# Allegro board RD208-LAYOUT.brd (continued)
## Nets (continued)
GD_U3: Q7.4 R178.2 R216.1 R247.2
GD_U4: Q9.4 R179.2 R217.1 R249.2
GD_U5: Q11.4 R180.2 R218.1 R251.2
GD_U6: Q13.4 R181.2 R219.1 R253.2
GD_U7: Q15.4 R182.2 R220.1 R255.2
GD_U8: Q17.4 R183.2 R221.1 R257.2
GD_V1: Q19.4 R168.2 R222.1 R258.2
GD_V2: Q21.4 R169.2 R223.1 R260.2
GD_V3: Q23.4 R170.2 R224.1 R262.2
GD_V4: Q25.4 R171.2 R225.1 R266.2
GD_V5: Q27.4 R172.2 R226.1 R264.2
GD_V6: Q29.4 R173.2 R227.1 R268.2
GD_V7: Q31.4 R174.2 R228.1 R270.2
GD_V8: Q33.4 R175.2 R229.1 R272.2
GD_W1: Q35.4 R184.2 R230.1 R274.2
GD_W2: Q37.4 R185.2 R231.1 R276.2
GD_W3: Q39.4 R186.2 R232.1 R278.2
GD_W4: Q41.4 R187.2 R233.1 R280.2
GD_W5: Q43.4 R188.2 R234.1 R282.2
GD_W6: Q45.4 R189.2 R235.1 R284.2
GD_W7: Q47.4 R190.2 R236.1 R286.2
GD_W8: Q49.4 R191.2 R237.1 R288.2
HVU_1_4: C54.2 C56.1 D19.3 D19.4 D25.5 R195.2 R196.1
HVU_2_4: C49.2 C54.1 D17.3 D17.4 D23.5 R194.2 R195.1
HVU_3_4: C48.2 C49.1 D15.3 D15.4 D21.5 R193.2 R194.1
HVV_1_4: C69.2 C71.1 D31.3 D31.4 D37.5 R201.2 R202.1
HVV_2_4: C65.2 C69.1 D29.3 D29.4 D35.5 R200.2 R201.1
HVV_3_4: C63.2 C65.1 D27.3 D27.4 D33.5 R199.2 R200.1
HVW_1_4: C82.2 C84.1 D43.3 D43.4 D49.5 R205.2 R206.1
HVW_2_4: C80.2 C82.1 D41.3 D41.4 D47.5 R204.2 R205.1
HVW_3_4: C78.2 C80.1 D39.3 D39.4 D45.5 R203.2 R204.1
ILIM_H: IC13.3 IC15.3 IC18.3 R129.2 R131.1
ILIM_L: IC13.6 IC15.6 IC18.6 R132.2 R134.1
ISEN_U: IC10.7 IC19.1 R309.2
ISEN_U_FLT: C139.1 IC13.2 IC13.5 R309.1
ISEN_V: IC11.7 IC20.1 R310.2
ISEN_V_FLT: C140.1 IC15.2 IC15.5 R310.1
ISEN_W: IC12.7 IC21.1 R311.2
ISEN_W_FLT: C141.1 IC18.2 IC18.5 R311.1
L3803_FB: IC3.3 R29.2 R34.1
L3803_NGATE: IC3.6 R154.1
L3803_SENSE: C103.1 IC3.4 R30.1
L3803_VCC: C129.1 IC3.5 R155.2
LDO_15V_CDC: IC2.3 R296.1
LDO_15V_ILIM: IC2.2 R26.1
LDO_15V_SET: IC2.5 R27.2 R296.2
LDO_15V_STD_N: IC2.12 R22.2
LDO_15VOUT: C16.1 IC2.6 IC2.7 R21.1 R24.2 R25.1 R295.1 R297.2 TP4.1
LT8316_BIAS: C4.1 IC1.9 R2.1
LT8316_DCM: IC1.10 R4.2
LT8316_EN: C8.2 IC1.17 R7.2 R11.2 R312.2
LT8316_FB: IC1.12 R6.2 R12.1 R13.1
LT8316_FB_B: C5.1 D1.1 R6.1 T3.5
LT8316_GATE: IC1.19 R17.1
LT8316_GATE_B: Q1.1 R17.2 R207.1
LT8316_INTVCC: C14.1 IC1.8 R312.1
LT8316_IREG: IC1.14 R16.2
LT8316_SENSE: C13.1 IC1.18 R18.1
LT8316_SENSE_B: Q1.2 Q1.3 Q1.4 R18.2 R19.1
LT8316_TC: IC1.11 R12.2
LT8316_VC: C10.1 IC1.13 R14.1
MCU_EMG: CN3.25 IC16.7
MCU_IU: C134.1 CN3.36 R137.1
MCU_IV: C135.1 CN3.38 R140.1
MCU_IW: C136.1 CN3.40 R143.1
MCU_MODE: IC6.14 R44.2 R166.1
MCU_RESET: IC6.13 R45.2 R167.1
MCU_RSV1: IC6.12 R46.2 R198.2
MCU_RSV2: IC6.11 R47.2 R238.2
MCU_RSV3: IC8.12 R64.2 R239.2
MCU_RSV4: IC8.11 R65.2 R240.2
MCU_TCK: IC6.17 R41.2 R160.1
MCU_TDI: IC6.16 R42.2 R161.1
MCU_TDO: IC6.18 R40.2 R156.2
MCU_TMS: IC6.15 R43.2 R165.1
MCU_UH: IC8.18 R58.2 R162.1
MCU_UL: IC8.17 R59.2 R157.2
MCU_VDC: C133.1 CN3.26 R192.2
MCU_VH: IC8.16 R60.2 R163.1
MCU_VL: IC8.15 R61.2 R158.2
MCU_WH: IC8.14 R62.2 R164.1
MCU_WL: IC8.13 R63.2 R159.2
OC_U: IC14.7 IC17.1
OC_U_N: IC13.7 IC14.2
OC_U_P: IC13.1 IC14.1
OC_UV: IC16.1 IC17.7
OC_V: IC14.3 IC17.2
OC_V_N: IC14.6 IC15.7
OC_V_P: IC14.5 IC15.1
OC_W: IC16.2 IC17.3
OC_W_N: IC17.6 IC18.7
OC_W_P: IC17.5 IC18.1
OSC_ST_N: C46.1 IC22.1 IC22.4 R74.2
OUT_U: CN5.1 DR1.1
OUT_V: CN5.2 DR2.1
OUT_W: CN5.3 DR3.1
PC_ANODE_U1: C142.1 PC1.1 R81.2 R337.1
PC_ANODE_U2: C143.1 PC2.1 R83.2 R338.1
PC_ANODE_U3: C144.1 PC3.1 R85.2 R339.1
PC_ANODE_U4: C145.1 PC4.1 R87.2 R340.1
PC_ANODE_U5: C146.1 PC5.1 R89.2 R341.1
PC_ANODE_U6: C147.1 PC6.1 R91.2 R342.1
PC_ANODE_U7: C148.1 PC7.1 R93.2 R343.1
PC_ANODE_U8: C149.1 PC8.1 R95.2 R344.1
PC_ANODE_V1: C150.1 PC9.1 R97.2 R345.1
PC_ANODE_V2: C151.1 PC10.1 R99.2 R346.1
PC_ANODE_V3: C152.1 PC11.1 R100.2 R347.1
PC_ANODE_V4: C153.1 PC12.1 R102.2 R348.1
PC_ANODE_V5: C154.1 PC13.1 R105.2 R349.1
PC_ANODE_V6: C155.1 PC14.1 R107.2 R350.1
PC_ANODE_V7: C156.1 PC15.1 R109.2 R351.1
PC_ANODE_V8: C157.1 PC16.1 R111.2 R352.1
PC_ANODE_W1: C158.1 PC17.1 R113.2 R353.1
PC_ANODE_W2: C159.1 PC18.1 R115.2 R354.1
PC_ANODE_W3: C160.1 PC19.1 R117.2 R355.1
PC_ANODE_W4: C161.1 PC20.1 R119.2 R356.1
PC_ANODE_W5: C162.1 PC21.1 R121.2 R357.1
PC_ANODE_W6: C163.1 PC22.1 R123.2 R358.1
PC_ANODE_W7: C164.1 PC23.1 R125.2 R359.1
PC_ANODE_W8: C165.1 PC24.1 R127.2 R360.1
PC_G_U1: C47.2 C112.2 D15.5 PC1.4 Q3.1 Q3.2 Q3.3 Q5.5 Q5.6 Q5.7 Q5.8 R214.2 TP65.1
PC_G_U2: C50.2 C113.2 D17.5 PC2.4 Q5.1 Q5.2 Q5.3 Q7.5 Q7.6 Q7.7 Q7.8 R215.2 TP66.1
PC_G_U3: C53.2 C114.2 D19.5 PC3.4 Q7.1 Q7.2 Q7.3 Q9.5 Q9.6 Q9.7 Q9.8 R216.2 TP67.1
PC_G_U5: C57.2 C116.2 D21.3 D21.4 PC5.4 Q11.1 Q11.2 Q11.3 Q13.5 Q13.6 Q13.7 Q13.8 R218.2 TP69.1
PC_G_U6: C58.2 C117.2 D23.3 D23.4 PC6.4 Q13.1 Q13.2 Q13.3 Q15.5 Q15.6 Q15.7 Q15.8 R219.2 TP70.1
PC_G_U7: C59.2 C118.2 D25.3 D25.4 PC7.4 Q15.1 Q15.2 Q15.3 Q17.5 Q17.6 Q17.7 Q17.8 R220.2 TP71.1
PC_G_U8: C60.2 C119.2 IC10.1 IC10.2 PC8.4 Q17.1 Q17.2 Q17.3 R221.2 TP72.1
PC_G_V1: C62.2 C104.2 D27.5 PC9.4 Q19.1 Q19.2 Q19.3 Q21.5 Q21.6 Q21.7 Q21.8 R222.2 TP73.1
PC_G_V2: C64.2 C105.2 D29.5 PC10.4 Q21.1 Q21.2 Q21.3 Q23.5 Q23.6 Q23.7 Q23.8 R223.2 TP74.1
PC_G_V3: C68.2 C106.2 D31.5 PC11.4 Q23.1 Q23.2 Q23.3 Q25.5 Q25.6 Q25.7 Q25.8 R224.2 TP75.1
PC_G_V5: C72.2 C108.2 D33.3 D33.4 PC13.4 Q27.1 Q27.2 Q27.3 Q29.5 Q29.6 Q29.7 Q29.8 R226.2 TP77.1
PC_G_V6: C73.2 C109.2 D35.3 D35.4 PC14.4 Q29.1 Q29.2 Q29.3 Q31.5 Q31.6 Q31.7 Q31.8 R227.2 TP78.1
PC_G_V7: C74.2 C110.2 D37.3 D37.4 PC15.4 Q31.1 Q31.2 Q31.3 Q33.5 Q33.6 Q33.7 Q33.8 R228.2 TP79.1
PC_G_V8: C76.2 C111.2 IC11.1 IC11.2 PC16.4 Q33.1 Q33.2 Q33.3 R229.2 TP80.1
PC_G_W1: C77.2 C120.2 D39.5 PC17.4 Q35.1 Q35.2 Q35.3 Q37.5 Q37.6 Q37.7 Q37.8 R230.2 TP81.1
PC_G_W2: C79.2 C121.2 D41.5 PC18.4 Q37.1 Q37.2 Q37.3 Q39.5 Q39.6 Q39.7 Q39.8 R231.2 TP82.1
PC_G_W3: C81.2 C122.2 D43.5 PC19.4 Q39.1 Q39.2 Q39.3 Q41.5 Q41.6 Q41.7 Q41.8 R232.2 TP83.1
PC_G_W5: C85.2 C124.2 D45.3 D45.4 PC21.4 Q43.1 Q43.2 Q43.3 Q45.5 Q45.6 Q45.7 Q45.8 R234.2 TP85.1
PC_G_W6: C86.2 C125.2 D47.3 D47.4 PC22.4 Q45.1 Q45.2 Q45.3 Q47.5 Q47.6 Q47.7 Q47.8 R235.2 TP86.1
PC_G_W7: C87.2 C126.2 D49.3 D49.4 PC23.4 Q47.1 Q47.2 Q47.3 Q49.5 Q49.6 Q49.7 Q49.8 R236.2 TP87.1
PC_G_W8: C88.2 C127.2 IC12.1 IC12.2 PC24.4 Q49.1 Q49.2 Q49.3 R237.2 TP88.1
PC_GD_U1: D50.K PC1.5 R176.1
PC_GD_U2: D51.K PC2.5 R177.1
PC_GD_U3: D52.K PC3.5 R178.1
PC_GD_U4: D53.K PC4.5 R179.1
PC_GD_U5: D54.K PC5.5 R180.1
PC_GD_U6: D55.K PC6.5 R181.1
PC_GD_U7: D56.K PC7.5 R182.1
PC_GD_U8: D57.K PC8.5 R183.1
PC_GD_V1: D58.K PC9.5 R168.1
PC_GD_V2: D59.K PC10.5 R169.1
PC_GD_V3: D60.K PC11.5 R170.1
PC_GD_V4: D62.K PC12.5 R171.1
PC_GD_V5: D61.K PC13.5 R172.1
PC_GD_V6: D63.K PC14.5 R173.1
PC_GD_V7: D64.K PC15.5 R174.1
PC_GD_V8: D65.K PC16.5 R175.1
PC_GD_W1: D66.K PC17.5 R184.1
PC_GD_W2: D67.K PC18.5 R185.1
PC_GD_W3: D68.K PC19.5 R186.1
PC_GD_W4: D69.K PC20.5 R187.1
PC_GD_W5: D70.K PC21.5 R188.1
PC_GD_W6: D71.K PC22.5 R189.1
PC_GD_W7: D72.K PC23.5 R190.1
PC_GD_W8: D73.K PC24.5 R191.1
PC_V_U1: C47.1 C112.1 PC1.6 R80.1 TP25.1
PC_V_U2: C50.1 C113.1 PC2.6 R82.1 TP26.1
PC_V_U3: C53.1 C114.1 PC3.6 R84.1 TP27.1
PC_V_U4: C55.1 C115.1 PC4.6 R86.1 TP28.1
PC_V_U5: C57.1 C116.1 PC5.6 R88.1 TP29.1
PC_V_U6: C58.1 C117.1 PC6.6 R90.1 TP30.1
PC_V_U7: C59.1 C118.1 PC7.6 R92.1 TP31.1
PC_V_U8: C60.1 C119.1 PC8.6 R94.1 TP32.1
PC_V_V1: C62.1 C104.1 PC9.6 R96.1 TP41.1
PC_V_V2: C64.1 C105.1 PC10.6 R98.1 TP42.1
PC_V_V3: C68.1 C106.1 PC11.6 R101.1 TP43.1
PC_V_V4: C70.1 C107.1 PC12.6 R103.1 TP44.1
PC_V_V5: C72.1 C108.1 PC13.6 R104.1 TP45.1
PC_V_V6: C73.1 C109.1 PC14.6 R106.1 TP46.1
PC_V_V7: C74.1 C110.1 PC15.6 R108.1 TP47.1
PC_V_V8: C76.1 C111.1 PC16.6 R110.1 TP48.1
PC_V_W1: C77.1 C120.1 PC17.6 R112.1 TP57.1
PC_V_W2: C79.1 C121.1 PC18.6 R114.1 TP58.1
PC_V_W3: C81.1 C122.1 PC19.6 R116.1 TP59.1
PC_V_W4: C83.1 C123.1 PC20.6 R118.1 TP60.1
PC_V_W5: C85.1 C124.1 PC21.6 R120.1 TP61.1
PC_V_W6: C86.1 C125.1 PC22.6 R122.1 TP62.1
PC_V_W7: C87.1 C126.1 PC23.6 R124.1 TP63.1
PC_V_W8: C88.1 C127.1 PC24.6 R126.1 TP64.1
PC_VGS_U1: C142.2 PC1.3 Q4.3 R337.2
PC_VGS_U2: C143.2 PC2.3 Q6.3 R338.2
PC_VGS_U3: C144.2 PC3.3 Q8.3 R339.2
PC_VGS_U4: C145.2 PC4.3 Q10.3 R340.2
PC_VGS_U5: C146.2 PC5.3 Q12.3 R341.2
PC_VGS_U6: C147.2 PC6.3 Q14.3 R342.2
PC_VGS_U7: C148.2 PC7.3 Q16.3 R343.2
PC_VGS_U8: C149.2 PC8.3 Q18.3 R344.2
PC_VGS_V1: C150.2 PC9.3 Q20.3 R345.2
PC_VGS_V2: C151.2 PC10.3 Q22.3 R346.2
PC_VGS_V3: C152.2 PC11.3 Q24.3 R347.2
PC_VGS_V4: C153.2 PC12.3 Q26.3 R348.2
PC_VGS_V5: C154.2 PC13.3 Q28.3 R349.2
PC_VGS_V6: C155.2 PC14.3 Q30.3 R350.2
PC_VGS_V7: C156.2 PC15.3 Q32.3 R351.2
PC_VGS_V8: C157.2 PC16.3 Q34.3 R352.2
PC_VGS_W1: C158.2 PC17.3 Q36.3 R353.2
PC_VGS_W2: C159.2 PC18.3 Q38.3 R354.2
PC_VGS_W3: C160.2 PC19.3 Q40.3 R355.2
PC_VGS_W4: C161.2 PC20.3 Q42.3 R356.2
PC_VGS_W5: C162.2 PC21.3 Q44.3 R357.2
PC_VGS_W6: C163.2 PC22.3 Q46.3 R358.2
PC_VGS_W7: C164.2 PC23.3 Q48.3 R359.2
PC_VGS_W8: C165.2 PC24.3 Q50.3 R360.2
TRANS2_AUX: D10.A T2.3
TRANS2_AUX_B: C21.1 D10.K R28.1 R31.1 R300.1
TRANS2_PRI: C128.1 Q2.5 Q2.6 Q2.7 Q2.8 T2.1
TRANS2_SEC1: D7.A T2.16
TRANS2_SEC2: D8.A T2.13
TRANS2_SEC3: D9.A T2.10
TRANS2_SEC4: D11.A T2.7
V_LH: C20.1 D11.K D20.A D22.A D24.A D32.A D34.A D36.A D44.A D46.A D48.A R94.2 R110.2 R126.2 R307.1 R308.1
V_UH: C17.1 D7.K D14.A D16.A D18.A R86.2 R301.1 R302.1
V_UL: C17.2 C55.2 C115.2 DR1.2 PC4.4 Q9.1 Q9.2 Q9.3 Q11.5 Q11.6 Q11.7 Q11.8 R217.2 R301.2 R302.2 T2.15 TP68.1
V_VH: C18.1 D8.K D26.A D28.A D30.A R103.2 R303.1 R304.1
V_VL: C18.2 C70.2 C107.2 DR2.2 PC12.4 Q25.1 Q25.2 Q25.3 Q27.5 Q27.6 Q27.7 Q27.8 R225.2 R303.2 R304.2 T2.12 TP76.1
V_WH: C19.1 D9.K D38.A D40.A D42.A R118.2 R305.1 R306.1
V_WL: C19.2 C83.2 C123.2 DR3.2 PC20.4 Q41.1 Q41.2 Q41.3 Q43.5 Q43.6 Q43.7 Q43.8 R233.2 R305.2 R306.2 T2.9 TP84.1
VDC: C11.1 C130.1 IC9.1 R10.2 R15.1
VDC_VF_OUT: IC9.3 IC9.4 R192.1
VP_1R8_CPLD_D: C30.1 C40.1 C41.1 C42.1 IC5.5 IC7.26 IC7.57 TP8.1
VP_3R3_PRH_D: C25.1 C31.1 C32.1 C33.1 C34.1 C35.1 C36.1 C37.1 C39.1 C44.1 C61.1 C75.1 C89.1 CN4.2 IC4.5 IC6.1 IC7.5 IC7.20 IC7.38 IC7.51 IC7.88 IC7.98 IC8.1 IC10.8 IC11.8 IC12.8 R48.1 R49.1 R50.1 R51.1 R52.1 R53.1 R54.1 R55.1 R66.1 R67.1 R68.1 R69.1 R70.1 R71.1 R72.1 R73.1 R74.1 R128.1 R129.1 R145.1 R146.1 R147.1 R148.1 R149.1 R150.1 R151.1 R152.1 R153.1 R241.1 R243.1 R289.2 R291.2 R293.2 TP7.1
VP_5R0_PRH_D: C27.1 C28.1 C29.1 C38.1 C43.1 C45.1 C90.1 C91.1 C92.1 C93.1 C94.1 C95.1 C97.1 C99.1 C101.1 FL1.3 IC4.1 IC5.1 IC6.20 IC8.20 IC9.5 IC13.8 IC14.8 IC15.8 IC16.8 IC17.8 IC18.8 IC19.5 IC20.5 IC21.5 R36.1 R39.1 R40.1 R41.1 R42.1 R43.1 R44.1 R45.1 R46.1 R47.1 R56.2 R57.2 R58.1 R59.1 R60.1 R61.1 R62.1 R63.1 R64.1 R65.1 R81.1 R83.1 R85.1 R87.1 R89.1 R91.1 R93.1 R95.1 R97.1 R99.1 R100.1 R102.1 R105.1 R107.1 R109.1 R111.1 R113.1 R115.1 R117.1 R119.1 R121.1 R123.1 R125.1 R127.1 TP6.1
VP_15R0_INV_ISO: C137.1 C138.1 R20.2 R21.2 R23.2 R25.2 R155.1 T2.2 TP5.1
VP_15R0_INV_LDO: C6.1 C7.1 C9.1 C15.1 C131.1 C132.1 D2.3 D3.K IC2.10 IC2.11 R8.2 R20.1 R22.1 R23.1 TP3.1
VP_400R0_INV: C1.1 C2.1 C3.1 C48.1 C63.1 C66.1 C67.1 C78.1 CN1.1 D4.A IC1.1 IC1.2 IC1.3 Q3.5 Q3.6 Q3.7 Q3.8 Q19.5 Q19.6 Q19.7 Q19.8 Q35.5 Q35.6 Q35.7 Q35.8 R1.1 R5.1 R193.1 R199.1 R203.1 T3.3 TP1.1
N757857: D6.A Q1.5 T3.1
N3161846: Q2.1 Q2.2 Q2.3 R30.2 R33.1
N3164696: C22.1 IC3.1
N3166714: C22.2 R32.1
N7602621: D1.2 R2.2
N15775681: R131.2 R133.1
N15775685: R133.2 R135.1
N15775892: R130.2 R132.1
N15776035: R128.2 R130.1
N15787951: IC6.19 R241.2 R242.2
N15791319: IC8.19 R243.2 R244.2
N15816177: CN3.20 R56.1
N15836565: CN3.28 R57.1
N15837078: CN3.10 R157.1
N15837084: CN3.12 R158.1
N15837090: CN3.14 R159.1
N15837096: CN3.4 R156.1
N15859536: IC10.6 R289.1 R290.1
N15862955: IC12.6 R293.1 R294.2
N15947158: R9.2 R10.1
N15947162: R5.2 R9.1
N15947280: R1.2 R3.1
N15947304: R3.2 R7.1
N15966322: IC22.3 R79.1
N15969728: DS1.A R145.2
N15969732: DS2.A R146.2
N15969736: DS3.A R147.2
N15969740: DS4.A R148.2
N15970009: R149.2 R210.1 S1.1
N15970013: R150.2 R211.1 S1.2
N15970017: R151.2 R212.1 S1.3
N15970021: R152.2 R213.1 S1.4
N15981855: C102.1 R153.2 R209.1 S2.1 S2.2
N16080427: Q2.4 R154.2 R208.1
N16084254: CN3.3 R160.2
N16084299: CN3.5 R161.2
N16084344: CN3.9 R162.2
N16084389: CN3.11 R163.2
N16084434: CN3.13 R164.2
N16084479: CN3.19 R165.2
N16084524: CN3.21 R166.2
N16084569: CN3.23 R167.2
N16128748: D2.1 D2.2 T3.8 T3.9
N16129695: D4.K D6.K
N16132048: CN3.6 R198.1
N16289804: C128.2 R197.1
N16355511: C5.2 R4.1
N16465335: IC4.3 R36.2
N16465385: IC5.3 R39.2
N16663040: CN3.8 R238.1
N16663424: CN3.22 R239.1
N16663428: CN3.24 R240.1
N16677268: D50.A R245.1
N16677456: D51.A R246.1
N16677751: D52.A R247.1
N16678100: D53.A R249.1
N16678365: D54.A R251.1
N16678572: D55.A R253.1
N16678779: D56.A R255.1
N16678984: D57.A R257.1
N16682431: D58.A R258.1
N16682896: D59.A R260.1
N16683103: D60.A R262.1
N16683312: D61.A R264.1
N16683534: D62.A R266.1
N16683743: D63.A R268.1
N16683946: D64.A R270.1
N16684168: D65.A R272.1
N16689205: D66.A R274.1
N16689414: D67.A R276.1
N16689619: D68.A R278.1
N16689826: D69.A R280.1
N16690061: D70.A R282.1
N16690281: D71.A R284.1
N16690501: D72.A R286.1
N16690719: D73.A R288.1
N16776249: IC11.6 R291.1 R292.2
N16781117: IC2.15 R295.2
N16783087: R24.1 R27.1
N16783507: IC2.4 R297.1
N159286810: C12.1 R14.2
N159479370: R28.2 R29.1

Pads without a net: CN3 7 17 18 27 30 32 34; CN4 12 14; D15 1 2; D17 1 2; D19 1 2; D21 1 2; D23 1 2; D25 1 2; D27 1 2; D29 1 2; D31 1 2; D33 1 2; D35 1 2; D37 1 2; D39 1 2; D41 1 2; D43 1 2; D45 1 2; D47 1 2; D49 1 2; IC2 13 14; IC4 4; IC5 4; IC7 1 2 3 4 6 15 16 17 18 19 29 37 39 40 41 42 43 44 46 59 63 64 74 86 87 97; IC16 3; T3 2 4 7 12

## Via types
v1: diameter 0.6, hole 0.3, TOP to BOTTOM, 502 vias
v2: diameter 0.8, hole 0.5, TOP to BOTTOM, 1431 vias
v3: diameter 1.6, hole 1, TOP to BOTTOM, 1 via

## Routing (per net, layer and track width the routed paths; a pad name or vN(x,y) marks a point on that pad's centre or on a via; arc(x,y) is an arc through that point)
GND: length 239.3
  TOP w0.35: IC1.21 48.8,18.98 52.1,18.98 v2(52.75,18.32) IC1.15 48.8,18.32 IC1.21 ; IC1.21 48.47,21.57 IC1.20 52.1,21.57 52.33,21.8 C13.2 ; IC2.1 IC2.16 ; IC2.9 IC2.8
  TOP w0.5: R26.2 162.85,30.95 ; C12.2 58.25,14.75
  TOP w0.6: v1(196.35,3.75) v1(197.35,3.75) ; 186,144.2 185.71,143.91 IC12.4 ; IC11.3 163.49,97.2 ; IC12.3 185.63,142.63 186,143 ; 164.85,97.25 164.75,97.34 IC11.4 ; IC10.4 58.25,59.24 ; IC10.3 58.25,60.52 ; v1(196.35,5.5) v1(197.35,5.5)
  TOP w0.8: R298.2 61.4,148.15 ; R298.2 R299.2 ; R298.2 60.25,147 ; R299.2 60.25,144.5 ; R299.2 61.4,143.5 ; C10.2 56.7,13.25 ; R207.2 v1(50.5,23.1) ; R16.1 56.7,16.25 ; R13.2 56.7,11.75
  TOP w1: C4.2 45.12,8.2 ; IC2.17 v2(157.5,37.5) ; v2(48.45,22.2) 48.45,19.85 ; 56.7,16.25 R19.2 ; R19.2 58.05,18.7 ; R19.2 v2(55.1,18.7) ; C15.2 154.4,38.85 ; C14.2 38.5,13.1 ; C16.2 161.1,38.95
  CONDUCTIVE4 w3: 54.1,138.85 54.1,134.85 46.65,127.4 46.65,63.65 34.75,51.75 C66.2
  BOTTOM w0.6: C138.2 v1(196.35,5.5) v1(197.35,5.5) ; v1(197.35,3.75) v1(196.35,3.75) C137.2 ; v1(189.5,25) IC3.2 191.9,25 v1(192.15,25.25) ; R31.2 v1(200.15,20.25) 200.6,19.8 C21.2 v1(201.8,18.25)
  BOTTOM w0.8: R32.2 v1(195.6,26.2) ; R197.2 v1(193.1,13.05) ; C20.2 224,13.9 R307.2 R308.2 ; R34.2 v1(195.25,24.05) ; R208.2 v1(191.3,16.9) ; R33.2 189.76,21.01 v1(189.95,21.2) C103.2 189.95,23.1 189.5,23.55 v1(189.5,25) 189.5,27.5 188.8,28.2 v1(187.7,28.2) C129.2 ; R11.1 49.5,15.7 ; C8.1 51,16 ; R300.2 R31.2
  BOTTOM w1: C20.2 T2.8
  BOTTOM w1.2: C56.2 11.85,87.4 R196.2
  BOTTOM w1.3: R206.2 227.35,128.6 C84.2 ; R202.2 156.1,56.35 C71.2
  vias: v2(10.7,11.5) v2(10.7,10.3) v2(10.7,9.1) v2(10.7,7.9) v2(10.7,6.7) v2(10.7,5.5) v2(11.9,11.5) v2(11.9,10.3) v2(11.9,9.1) v2(11.9,7.9) v2(11.9,6.7) v2(11.9,5.5) v2(13.1,11.5) v2(13.1,10.3) v2(13.1,9.1) v2(13.1,7.9) v2(13.1,6.7) v2(13.1,5.5) v2(14.3,11.5) v2(14.3,10.3) v2(14.3,9.1) v2(14.3,7.9) v2(14.3,6.7) v2(14.3,5.5) v2(15.5,11.5) v2(15.5,10.3) v2(15.5,9.1) v2(15.5,7.9) v2(15.5,6.7) v2(15.5,5.5) v2(16.7,11.5) v2(16.7,10.3) v2(16.7,9.1) v2(16.7,7.9) v2(16.7,6.7) v2(16.7,5.5) v2(17.9,11.5) v2(17.9,10.3) v2(17.9,9.1) v2(17.9,7.9) v2(17.9,6.7) v2(17.9,5.5) v2(19.1,11.5) v2(19.1,10.3) v2(19.1,9.1) v2(19.1,7.9) v2(19.1,6.7) v2(19.1,5.5) v2(27.6,7.6) v2(27.6,6.4) v2(27.6,5.2) v2(27.6,4) v2(27.6,2.8) v2(28.7,61.85) v2(28.7,60.65) v2(28.7,59.45) v2(28.7,58.25) v2(28.7,57.05) v2(28.7,55.85) v2(28.8,7.6) v2(28.8,6.4) v2(28.8,5.2) v2(28.8,4) v2(28.8,2.8) v2(29.9,61.85) v2(29.9,60.65) v2(29.9,59.45) v2(29.9,58.25) v2(29.9,57.05) v2(29.9,55.85) v2(30,7.6) v2(30,6.4) v2(30,5.2) v2(30,4) v2(30,2.8) v2(31.1,61.85) v2(31.1,60.65) v2(31.1,59.45) v2(31.1,58.25) v2(31.1,57.05) v2(31.1,55.85) v2(31.2,7.6) v2(31.2,6.4) v2(31.2,5.2) v2(31.2,4) v2(31.2,2.8) v2(32.3,61.85) v2(32.3,60.65) v2(32.3,59.45) v2(32.3,58.25) v2(32.3,57.05) v2(32.3,55.85) v2(32.4,8.8) v2(32.4,7.6) v2(32.4,6.4) v2(32.4,5.2) v2(32.4,4) v2(32.4,2.8) v2(33.5,61.85) v2(33.5,60.65) v2(33.5,59.45) v2(33.5,58.25) v2(33.5,57.05) v2(33.5,55.85) v2(33.6,8.8) v2(33.6,7.6) v2(33.6,6.4) v2(33.6,5.2) v2(33.6,4) v2(33.6,2.8) v2(34.7,61.85) v2(34.7,60.65) v2(34.7,59.45) v2(34.7,58.25) v2(34.7,57.05) v2(34.7,55.85) v2(34.8,8.8) v2(34.8,7.6) v2(34.8,6.4) v2(34.8,5.2) v2(34.8,4) v2(34.8,2.8) v2(35.9,61.85) v2(35.9,60.65) v2(35.9,59.45) v2(35.9,58.25) v2(35.9,57.05) v2(36,12.4) v2(36,11.2) v2(36,10) v2(36,8.8) v2(36,7.6) v2(36,6.4) v2(36,5.2) v2(36,4) v2(36,2.8) v2(37.2,12.4) v2(37.2,11.2) v2(37.2,10) v2(37.2,8.8) v2(37.2,7.6) v2(37.2,4) v2(37.2,2.8) v2(38.4,12.4) v2(38.4,11.2) v2(38.4,10) v2(38.4,8.8) v2(38.4,7.6) v2(38.4,4) v2(38.4,2.8) v2(39.6,8.8) v2(39.6,7.6) v2(39.6,6.4) v2(39.6,5.2) v2(39.6,4) v2(39.6,2.8) v2(40.8,8.8) v2(40.8,7.6) v2(40.8,6.4) v2(40.8,5.2) v2(40.8,4) v2(40.8,2.8) v2(42,8.8) v2(42,7.6) v2(42,6.4) v2(42,5.2) v2(42,4) v2(42,2.8) v2(46.15,14.75) v2(47.35,14.75) v2(48.55,14.75) v2(49.75,14.75) v2(53.9,18.7) v2(53.9,17.5) v2(55.1,17.5) v2(57.85,148.1) v2(57.85,146.9) v2(59.05,148.1) v2(59.05,146.9) v2(60.25,148.1) v2(60.25,146.9) v2(61.7,7.5) v2(61.7,6.3) v2(61.7,5.1) v2(61.7,3.9) v2(61.7,2.7) v2(62.9,7.5) v2(62.9,6.3) v2(62.9,5.1) v2(62.9,3.9) v2(62.9,2.7) v2(64.1,7.5) v2(64.1,6.3) v2(64.1,5.1) v2(64.1,3.9) v2(64.1,2.7) v2(65.3,7.5) v2(65.3,6.3) v2(65.3,5.1) v2(65.3,3.9) v2(65.3,2.7) v2(66.5,7.5) v2(66.5,6.3) v2(66.5,5.1) v2(66.5,3.9) v2(66.5,2.7) v2(99.1,25.45) v2(99.1,24.25) v2(99.1,23.05) v2(99.1,21.85) v2(99.1,20.65) v2(100.3,25.45) v2(100.3,24.25) v2(100.3,23.05) v2(100.3,21.85) v2(100.3,20.65) v2(155.1,37.5) v2(155.1,31) v2(156.3,37.5) v2(156.3,31) v2(157.5,31) v2(158.7,37.5) v2(158.7,31) v2(159.9,37.5) v2(159.9,31) v2(164.75,97.25) v2(164.75,96.05) v2(164.75,94.85) v2(164.75,93.65) v2(165.95,97.25) v2(165.95,96.05) v2(165.95,94.85) v2(165.95,93.65) v2(165.95,92.45) v2(167.15,98.45) v2(167.15,97.25) v2(167.15,96.05) v2(167.15,94.85) v2(167.15,93.65) v2(167.15,92.45) v2(167.15,91.25) v2(168.35,98.45) v2(168.35,97.25) v2(168.35,96.05) v2(168.35,94.85) v2(168.35,93.65) v2(168.35,92.45) v2(168.35,91.25) v2(168.35,90.05) v2(169.55,98.45) v2(169.55,97.25) v2(169.55,96.05) v2(169.55,94.85) v2(169.55,93.65) v2(169.55,92.45) v2(169.55,91.25) v2(169.55,90.05) v2(169.55,88.85) v2(170.75,97.25) v2(170.75,96.05) v2(170.75,94.85) v2(170.75,93.65) v2(170.75,92.45) v2(170.75,91.25) v2(170.75,90.05) v2(170.75,88.85) v2(186,147.9) v2(186,146.7) v2(186,145.5) v2(186,144.3) v2(186,143.1) v2(187.2,147.9) v2(187.2,146.7) v2(187.2,145.5) v2(187.2,144.3) v2(187.2,143.1) v2(188.4,147.9) v2(188.4,146.7) v2(188.4,145.5) v2(188.4,144.3) v2(188.4,143.1) v2(189.6,147.9) v2(189.6,146.7) v2(189.6,145.5) v2(189.6,144.3) v2(189.6,143.1) v2(190.8,147.9) v2(190.8,146.7) v2(190.8,145.5) v2(190.8,144.3) v2(190.8,143.1) v2(192,147.9) v2(192,146.7) v2(192,145.5) v2(192,144.3) v2(192,143.1) v2(193.2,147.9) v2(193.2,146.7) v2(193.2,145.5) v2(193.2,144.3) v2(193.2,143.1) v2(194.4,147.9) v2(194.4,146.7) v2(194.4,145.5) v2(194.4,144.3) v2(194.4,143.1) v2(201.25,148) v2(201.25,146.75) v2(201.25,145.5) v2(201.25,144.25) v2(201.25,143) v2(201.25,141.75) v2(201.25,140.5) v2(202.5,148) v2(202.5,146.75) v2(202.5,145.5) v2(202.5,144.25) v2(202.5,143) v2(202.5,141.75) v2(202.5,140.5) v2(203.75,148) v2(203.75,146.75) v2(203.75,145.5) v2(203.75,144.25) v2(203.75,143) v2(203.75,141.75) v2(203.75,140.5) v2(205,148) v2(205,146.75) v2(205,145.5) v2(205,144.25) v2(205,143) v2(205,141.75) v2(205,140.5) v2(206.25,143) v2(206.25,141.75) v2(206.25,140.5) v2(207.5,140.5) v2(208.75,140.5) v2(210,140.5) v2(211.25,140.5) v2(212.5,140.5) v2(213.75,143) v2(213.75,141.75) v2(213.75,140.5) v2(215,148) v2(215,146.75) v2(215,145.5) v2(215,144.25) v2(215,143) v2(215,141.75) v2(215,140.5) v2(216.25,148) v2(216.25,146.75) v2(216.25,145.5) v2(216.25,144.25) v2(216.25,143) v2(216.25,141.75) v2(216.25,140.5) v2(217.5,148) v2(217.5,146.75) v2(217.5,145.5) v2(217.5,144.25) v2(217.5,143) v2(217.5,141.75) v2(217.5,140.5) v2(218.75,148) v2(218.75,146.75) v2(218.75,145.5) v2(218.75,144.25) v2(218.75,143) v2(218.75,141.75) v2(218.75,140.5)
GND_D: length 320.4
  TOP w0.2: IC14.4 v1(164.65,120.5) ; IC13.4 166.75,125.5 v1(166.75,125.95) ; IC17.4 v1(157.9,120.5) ; v1(159,125.95) 159,125.5 IC15.4 ; IC16.4 v1(151.15,120.5) ; IC18.4 151.25,125.5 v1(151.25,126.05) ; IC16.6 148.5,120 148.3,120.2 v1(148.3,120.55) 148.75,120.5 IC16.5
  TOP w0.3: 102.6,120.5 IC7.75 v1(99.9,120.5) ; v1(115.5,130.5) IC7.21 118.3,130.5 C33.2 ; 139.5,113.15 129.3,113.15 ; v1(106.8,116.95) 106.8,117.65 107,117.85 IC7.84 v1(107,120.05) ; IC7.31 v1(112.5,133) ; v1(99.9,123.5) IC7.69 102.6,123.5 ; v1(115.5,132.2) 115.8,132.5 IC7.25 ; v1(99.55,126.25) 100.3,127 IC7.62 102.25,127 v1(102.75,126.5) ; IC7.100 C37.2
  TOP w0.35: IC8.10 v1(133.05,131.82) ; IC6.10 v1(133.45,122.83)
  TOP w0.4: R144.1 154.2,130 ; R144.1 IC21.2 v1(151,130) ; R144.1 153.25,129.25 ; v1(155.5,130) IC20.2 R141.1 158.65,130 ; v1(164.5,130) IC9.2 166.65,130 ; v1(160,130) IC19.2 R138.1 163.1,130
  TOP w0.5: C34.2 v1(107.15,135.75) ; IC10.5 v1(66.35,59.24) 66.61,59.5 R290.2 ; v1(151.15,120.5) 150.5,119.85 C94.2 150.5,116.9 ; C135.2 v1(156.7,134.05) ; CN4.7 CN4.9 ; CN4.7 CN4.5 ; CN4.7 105.5,148.15 ; CN4.9 103.5,148.15 ; CN4.9 CN4.11 101.5,148.15 ; C39.2 133.6,130 v1(133.6,130.15) ; C43.2 v1(135.9,139) ; CN4.3 CN4.5 ; CN4.3 CN4.1 ; CN4.3 109.5,148.2 ; CN4.5 107.5,148.15 ; C32.2 v1(118.25,120.65) ; 166,121.95 C90.2 166,125.2 v1(166.75,125.95) ; C61.2 v1(67.4,62.15) ; C37.2 v1(115.85,117.25) ; C141.2 v1(153.15,122.6) ; 164,116.9 C91.2 164,119.85 v1(164.65,120.5) ; v1(116.4,136.65) 116.1,136.35 C42.2 ; C102.2 129.95,116.15 S2.5 ; R294.1 177.4,143.65 v1(177.65,143.91) IC12.5 ; C99.2 v1(155.5,130) ; C35.2 v1(99.75,134.35) ; C75.2 v1(161.85,106.65) ; v1(157.9,120.5) 157.25,119.85 C93.2 157.25,116.9 ; v1(159,125.95) 158.25,125.2 C92.2 158.25,121.95 ; 99.5,148.15 CN4.13 98,146.75 ; C36.2 v1(108,116.35) ; C136.2 v1(152.2,134) ; C46.2 v1(120.5,128.1) ; CN4.1 112.85,146.75 ; CN4.1 111.5,148.15 ; C45.2 v1(164.5,130) ; C101.2 v1(151,130) ; C41.2 v1(99.35,127.55) ; C97.2 v1(160,130) ; v1(151.25,126.05) 150.5,125.3 C95.2 150.5,122 ; v1(133.6,139.25) 133.6,139 C44.2 ; C139.2 v1(168.65,122.6) ; IC11.5 v1(164.75,105.6) 164.5,105.86 R292.1 ; C38.2 v1(135.65,130) ; C133.2 v1(163.5,133.9) ; C140.2 v1(160.9,122.6) ; C89.2 v1(176.6,141) ; C134.2 v1(161.2,134)
  TOP w0.6: v1(99.35,127.55) 98.25,127.55 C40.2 v1(97.05,127.7) ; 150.45,109.25 v1(143.3,109.25) v1(134.05,109.25) v1(124.8,109.25) ; S1.5 v1(92.91,136.8) ; C102.2 v1(128.5,117.2) ; CN3.37 v1(147.96,148.4) ; C28.2 v1(90.15,119.2) 90.25,119.1 C25.2 ; CN3.33 v1(150.5,148.4) ; R135.2 v1(144.5,128.65) ; IC4.2 v1(87.5,117.5) ; S2.4 v1(128.5,118.75) ; S2.3 v1(140.15,118.75) ; C30.2 80.75,119.1 v1(80.6,119.25) C29.2 ; CN3.39 v1(146.69,148.4) ; S1.8 v1(89.09,136.8) ; CN3.35 v1(149.22,148.4) ; C31.2 v1(99.75,134.35) ; S1.6 v1(91.64,136.8) ; IC22.2 v1(125.75,131.05) ; v1(70.85,125.6) v1(70.85,121.8) ; CN3.29 v1(153.03,148.4) ; S1.7 v1(90.36,136.8) ; R134.2 v1(146,128.65) ; IC5.2 v1(78,117.5) ; CN3.31 v1(151.76,148.4)
  TOP w0.7: v1(170.81,142.75) CN3.2 CN3.1 v1(170.81,148.4) ; CN3.15 v1(161.93,145.7) CN3.16 v1(161.93,142.75)
  TOP w0.8: R299.1 63.1,143.5 ; R299.1 R298.1 ; R299.1 64.25,144.5 ; R298.1 64.35,147 ; R298.1 63.1,148.15
  CONDUCTIVE2 w0.2: 178.5,77.55 v1(179.2,77.55) ; 178.65,86.8 v1(179.2,86.8) ; 178.55,96.05 v1(179.2,96.05) ; 178.25,68.3 v1(179.2,68.3)
  CONDUCTIVE2 w0.5: v1(120.5,128.1) 120.5,127.1 120.85,126.75 126.45,126.75 126.75,127.05 126.75,130.85 126.55,131.05 v1(125.75,131.05)
  CONDUCTIVE3 w0.2: 178.55,77.55 v1(179.2,77.55) ; 178.45,86.8 v1(179.2,86.8) ; 178.45,68.3 v1(179.2,68.3) ; 178.75,109.2 v1(178.75,108.5) ; 178.55,96.05 v1(179.2,96.05)
  CONDUCTIVE4 w0.2: 178.6,68.3 v1(179.2,68.3) ; 178.5,86.8 v1(179.2,86.8) ; 178.5,77.55 v1(179.2,77.55) ; 178.5,96.05 v1(179.2,96.05) ; 108,117.1 v1(108,116.35)
  CONDUCTIVE5 w0.2: 178.45,86.8 v1(179.2,86.8) ; 178.55,77.55 v1(179.2,77.55) ; 178.45,96.05 v1(179.2,96.05) ; 178.35,68.3 v1(179.2,68.3)
  BOTTOM w0.2: 136.9,127.55 137.05,127.7 137.05,128.6 137,128.65
  BOTTOM w0.5: CN4.7 105.5,148.25 ; CN4.7 CN4.5 ; CN4.7 CN4.9 ; v1(66.5,75.5) R319.2 Q16.2 ; v1(117.1,105.9) R324.2 Q26.2 ; CN4.1 113.1,146.75 ; CN4.1 111.5,148.25 ; CN4.1 CN4.3 ; Q46.2 R334.2 v1(176.5,119.25) ; Q38.2 R330.2 178.75,77.1 v1(179.2,77.55) ; v3(101,115.5) 101,114.25 ; v3(101,115.5) 102.25,115.5 ; v3(101,115.5) 101,116.75 ; v3(101,115.5) 99.75,115.5 ; 98.05,146.75 CN4.13 99.5,148.25 ; Q48.2 R335.2 v1(176.5,128.5) ; v1(66.65,116.15) R315.2 Q8.2 ; CN4.3 CN4.5 ; CN4.3 109.5,148.25 ; CN4.5 107.5,148.25 ; v1(66.65,125.4) R314.2 Q6.2 ; v1(98.6,105.9) R322.2 Q22.2 ; v1(152.55,109.25) 152.7,109.4 R328.2 Q34.2 ; v1(66.65,134.65) R313.2 Q4.2 ; Q28.2 R325.2 124.95,109.4 v1(124.8,109.25) ; v1(179.2,96.05) 178.75,95.6 R332.2 Q42.2 ; v1(143.3,109.25) 143.45,109.4 R327.2 Q32.2 ; CN4.9 CN4.11 101.5,148.25 ; CN4.9 103.5,148.25 ; v1(179.2,86.8) 178.75,86.35 R331.2 Q40.2 ; Q20.2 R321.2 v1(89.35,105.9) ; v1(179.2,68.3) 178.75,67.85 R329.2 Q36.2 ; Q24.2 R323.2 v1(107.85,105.9) ; Q10.2 R316.2 v1(66.65,106.9) ; v1(66.5,84.75) R318.2 Q14.2 ; R244.1 v1(133.6,136) ; Q12.2 R317.2 v1(66.5,94) ; v1(134.05,109.25) 134.2,109.4 R326.2 Q30.2 ; v1(176.5,110) R333.2 Q44.2 ; Q50.2 R336.2 v1(176.5,137.75) ; R242.1 v1(133.6,127) ; Q18.2 R320.2 67.35,65.3
  BOTTOM w0.6: v1(166.75,125.95) 167.3,126.5 v1(168.35,126.5)
  vias: v1(65,140.25) v1(65,66.75) v1(65,64) v1(65.25,135.25) v1(65.25,131) v1(65.25,125.75) v1(65.25,121.75) v1(65.25,116.5) v1(65.25,112.5) v1(66.75,103.75) v1(68,144) v1(68.05,65.35) v1(70,147.75) v1(70.3,106.9) v1(70.75,139) v1(70.75,116.5) v1(71,135) v1(71,129.75) v1(72.25,104.5) v1(73,124.75) v1(73,118.25) v1(74.25,112.5) v1(76.5,124.75) v1(76.75,114.5) v1(77.5,109.75) v1(77.5,104.25) v1(79,106.75) v1(81.5,121.5) v1(81.5,109.75) v1(83,124.75) v1(83,114.75) v1(83.5,104.25) v1(84.75,110.25) v1(85,116.25) v1(87,121.5) v1(87.25,125) v1(87.75,132.5) v1(88,148.25) v1(88,143) v1(88,138) v1(88.75,104.25) v1(89.25,109.75) v1(91.5,123.25) v1(92.75,148.25) v1(92.75,143) v1(92.75,104.25) v1(94,118.25) v1(94.1,127.1) v1(94.25,109.75) v1(94.75,139.25) v1(95,133.25) v1(96.5,124.25) v1(97.5,148.25) v1(97.5,143) v1(98,104.25) v1(98.65,110.7) v1(101.4,110.7) v1(102,137.25) v1(102.25,142.75) v1(102.25,104.25) v1(103,129.75) v1(103.5,131.75) v1(103.5,109.75) v1(104.5,140.25) v1(104.8,115.05) v1(105.25,123) v1(107.25,104.25) v1(107.5,132.5) v1(107.75,138.25) v1(107.75,110.5) v1(108.5,129.5) v1(109.25,126.5) v1(110.25,143) v1(110.75,137.75) v1(110.75,127.75) v1(111.5,104.25) v1(112.5,140.5) v1(112.55,110) v1(114,148.25) v1(114,144) v1(114.75,127.25) v1(115,123.25) v1(116,140.25) v1(118.1,105.9) v1(119.3,131.75) v1(119.5,128.85) v1(120.75,116.75) v1(121.75,106) v1(122.75,139.5) v1(122.75,137) v1(125,120) v1(125.5,116.5) v1(125.75,127.75) v1(126,148.25) v1(126,143) v1(126,137) v1(125.95,132.15) v1(126,125.6) v1(130.95,106.3) v1(131,148) v1(131,143.75) v1(133.75,120.25) v1(136.25,148) v1(136.25,143.75) v1(137.75,142.25) v1(138,121.5) v1(139.35,106.1) v1(142.85,148) v1(143.5,132.3) v1(143.55,135.25) v1(143.75,146.25) v1(143.75,113.3) v1(145,139.15) v1(146.5,137.2) v1(147,119.65) v1(147.45,140.6) v1(147.5,126.25) v1(147.65,131.55) v1(148.05,123.2) v1(148.85,137.55) v1(148.75,113.3) v1(149.45,106) v1(150,140.65) v1(151,132) v1(151.4,123.1) v1(151.75,115.25) v1(151.95,135.95) v1(152.45,139.25) v1(153.75,113.3) v1(155.1,135.9) v1(155.1,118.75) v1(155.7,132) v1(156.3,139.15) v1(157,105.75) v1(158.1,139.7) v1(158.7,107.65) v1(158.75,113.3) v1(159,135.9) v1(159.15,123.05) v1(160.25,132) v1(160.25,115.25) v1(162.1,135.9) v1(163.25,113.3) v1(164.4,139.7) v1(165.6,136.1) v1(165.75,132.75) v1(166,115.75) v1(166.75,118) v1(166.95,123.05) v1(167.65,129.6) v1(168,113.3) v1(168.05,127.95) v1(168.8,121.35) v1(168.9,139.95) v1(169.65,127.8) v1(170,105.5) v1(170.35,132.35) v1(170.4,138.65) v1(170.75,111.25) v1(171,115.75) v1(171.25,121.25) v1(172.15,138.15) v1(173,132.25) v1(173,127.25) v1(173.25,123.25) v1(173.3,118.4) v1(174.05,142.55) v1(175,148.25) v1(178.75,112.75) v1(179,148.25) v1(179,145.25) v1(179,139) v1(179,136.25) v1(179,131.25) v1(179,127) v1(179,121.75) v1(179,117.75) v1(179,103.5) v2(64.25,147.6) v2(64.25,146.4) v2(65.5,147.6) v2(65.5,146.4) v2(66.7,147.6) v2(66.7,146.4)
AMP_IU_NI: length 3.3
  TOP w0.2: R136.2 C96.2 R138.2 161.7,131 161.35,130.65 IC19.3
AMP_IU_OUT: length 4.8
  TOP w0.2: R137.2 R136.1 C96.1 159.9,130.65 IC19.4
AMP_IV_NI: length 3.3
  TOP w0.2: IC20.3 156.85,130.65 157.2,131 R141.2 C98.2 R139.2
AMP_IV_OUT: length 4.8
  TOP w0.2: R140.2 R139.1 C98.1 155.4,130.65 IC20.4
AMP_IW_NI: length 3.3
  TOP w0.2: R142.2 C100.2 R144.2 152.7,131 152.35,130.65 IC21.3
AMP_IW_OUT: length 4.8
  TOP w0.2: IC21.4 150.9,130.65 C100.1 R142.1 R143.2
BS_U1: length 3.7
  BOTTOM w0.8: D14.K 49.55,140.25 R80.2
BS_U2: length 1.6
  BOTTOM w0.8: R82.2 53.55,132.6 D16.K
BS_U3: length 1.6
  BOTTOM w0.8: D18.K 53.55,123.35 R84.2
BS_U5: length 1.6
  BOTTOM w0.8: R88.2 53.55,101.25 D20.K
BS_U6: length 1.6
  BOTTOM w0.8: R90.2 53.55,92 D22.K
BS_U7: length 1.6
  BOTTOM w0.8: R92.2 53.55,82.75 D24.K
BS_V1: length 3.7
  BOTTOM w0.8: R96.2 83.75,88.8 D26.K
BS_V2: length 1.6
  BOTTOM w0.8: R98.2 91.4,92.8 D28.K
BS_V3: length 1.6
  BOTTOM w0.8: D30.K 100.65,92.8 R101.2
BS_V5: length 1.6
  BOTTOM w0.8: R104.2 122.75,92.8 D32.K
BS_V6: length 1.6
  BOTTOM w0.8: R106.2 132,92.8 D34.K
BS_V7: length 1.6
  BOTTOM w0.8: R108.2 141.25,92.8 D36.K
BS_W1: length 1.6
  BOTTOM w0.8: R112.2 190.45,61.3 D38.K
BS_W2: length 1.6
  BOTTOM w0.8: R114.2 190.45,70.55 D40.K
BS_W3: length 1.6
  BOTTOM w0.8: R116.2 190.45,79.8 D42.K
BS_W5: length 2.6
  BOTTOM w0.8: R120.2 193.35,106.85 D44.K
BS_W6: length 1.6
  BOTTOM w0.8: R122.2 190.45,111.15 D46.K
BS_W7: length 1.6
  BOTTOM w0.8: R124.2 190.45,120.4 D48.K
CN_TCK: length 3
  TOP w0.2: R75.1 CN4.6
CN_TDI: length 3
  TOP w0.2: R78.1 CN4.10
CN_TDO: length 3
  TOP w0.2: R77.1 CN4.8
CN_TMS: length 3
  TOP w0.2: R76.1 CN4.4
CP_MODE: length 26.1
  TOP w0.2: R52.2 v1(129.85,125.25) 130.26,125.42 IC6.6 ; v1(119.6,123.4) 117.9,123.4 117.8,123.5 IC7.7
  BOTTOM w0.2: v1(129.85,125.25) 131.25,123.85 131.25,121.55 130.15,120.45 126.1,120.45 124.3,122.25 124.3,124.35 123.3,125.35 122.25,125.35 120.3,123.4 v1(119.6,123.4)
CP_RESET: length 24.3
  TOP w0.2: R53.2 v1(129.85,124.25) 130.38,124.78 IC6.7 ; IC7.8 v1(118.8,124)
  BOTTOM w0.2: v1(129.85,124.25) 130.85,123.25 130.85,121.75 129.95,120.85 126.3,120.85 124.7,122.45 124.7,124.55 123.5,125.75 122.05,125.75 120.3,124 v1(118.8,124)
CP_RSV1: length 22.5
  TOP w0.2: IC6.8 130.72,124.12 v1(129.85,123.25) R54.2 ; IC7.9 117.75,124.5 117.85,124.6 v1(119.6,124.6)
  BOTTOM w0.2: v1(119.6,124.6) 120.3,124.6 121.85,126.15 123.7,126.15 125.1,124.75 125.1,122.65 126.5,121.25 129.75,121.25 130.45,121.95 130.45,122.65 v1(129.85,123.25)
CP_RSV2: length 20.6
  TOP w0.2: IC7.10 118.4,125 v1(118.8,125.2) ; R55.2 v1(129.85,122.25) 130.55,122.95 130.55,123.28 130.75,123.47 IC6.9
  BOTTOM w0.2: v1(129.85,122.25) 129.25,121.65 126.7,121.65 125.5,122.85 125.5,124.95 123.9,126.55 121.65,126.55 120.3,125.2 v1(118.8,125.2)
CP_RSV3: length 34.5
  TOP w0.2: v1(102.75,128.5) 102.25,128 IC7.60 ; R72.2 v1(129.85,132.25) 130.72,133.12 IC8.8
  BOTTOM w0.2: v1(102.75,128.5) 109.2,128.5 114.2,133.5 128.5,133.5 129.49,132.51 v1(129.85,132.25)
CP_RSV4: length 35.2
  TOP w0.2: IC8.9 130.75,132.47 130.55,132.28 130.55,131.95 v1(129.85,131.25) R73.2 ; IC7.61 v1(102.75,127.5)
  BOTTOM w0.2: v1(102.75,127.5) 108.85,127.5 114.45,133.1 128,133.1 v1(129.85,131.25)
CP_SW: length 13.9
  TOP w0.2: IC7.99 114.5,119.65 114.7,119.85 115.3,119.85 120.65,114.5 R209.2
CP_TCK: length 74.3
  TOP w0.2: IC7.48 v1(104,136.7) 107.5,140.2 R75.2 ; IC6.3 130.72,127.38 v1(129.85,128.25) R49.2
  BOTTOM w0.2: v1(104,136.7) 100.8,133.5 100.8,124.45 104.2,121.05 114.2,121.05 121.25,114 129.8,114 132.45,116.65 132.45,125.65 v1(129.85,128.25)
CP_TDI: length 71.6
  TOP w0.2: R50.2 v1(129.85,127.25) 130.38,126.72 IC6.4 ; IC7.45 v1(105.5,136.2) ; R78.2 v1(103.5,139.9)
  BOTTOM w0.2: v1(103.5,139.9) 105.5,137.9 v1(105.5,136.2) 104.35,136.2 101.2,133.05 101.2,124.7 104.45,121.45 114.4,121.45 121.45,114.4 129.6,114.4 132.05,116.85 132.05,125.05 v1(129.85,127.25)
CP_TDO: length 76.2
  TOP w0.2: R48.2 v1(129.85,129.25) 130.65,128.45 130.65,128.2 130.82,128.03 IC6.2 ; IC7.83 106.5,119.55 v1(106,120.05) ; R77.2 105.5,139.2 v1(103,136.7)
  BOTTOM w0.2: v1(103,136.7) 100.4,134.1 100.4,124.15 104.5,120.05 v1(106,120.05) 106.6,120.65 114,120.65 121.05,113.6 130,113.6 132.85,116.45 132.85,126.25 v1(129.85,129.25)
CP_TMS: length 69
  TOP w0.2: IC7.47 104.5,135.16 v1(104.6,135.6) 104.6,136.45 107.7,139.55 108.9,139.55 109.5,140.15 R76.2 ; IC6.5 130.26,126.08 v1(129.85,126.25) R51.2
  BOTTOM w0.2: v1(129.85,126.25) 131.65,124.45 131.65,117.05 129.4,114.8 121.65,114.8 114.55,121.9 104.65,121.9 101.6,124.95 101.6,132.6 v1(104.6,135.6)
CP_TP9: length 13.2
  TOP w0.2: IC7.11 118.2,125.5 118.5,125.8 119.4,125.8 120.2,125 120.2,119.3 TP9.1
CP_TP10: length 11.1
  TOP w0.2: IC7.12 118.1,126 118.3,126.2 119.6,126.2 120.6,125.2 120.6,121.4 TP10.1
CP_TP11: length 9.1
  TOP w0.2: IC7.13 118,126.5 118.1,126.6 119.8,126.6 121,125.4 121,123.5 TP11.1
CP_TP12: length 7.1
  TOP w0.2: IC7.14 120,127 TP12.1
CP_TP13: length 8.9
  TOP w0.2: IC7.23 117.95,131.5 118.4,131.95 118.4,135.4 TP13.1
CP_TP14: length 7.2
  TOP w0.2: IC7.24 117.75,132 118,132.25 118,136.91 TP14.1
CP_TP15: length 4.4
  TOP w0.2: IC7.27 114.5,137.25 TP15.1
CP_TP16: length 4.4
  TOP w0.2: IC7.28 114,137.25 TP16.1
CP_UH: length 24.1
  TOP w0.2: IC8.2 130.82,137.03 130.65,137.2 130.65,137.45 v1(129.85,138.25) R66.2 ; v1(112.9,136.75) 113,136.31 IC7.30
  BOTTOM w0.2: v1(129.85,138.25) 127.55,135.95 113.7,135.95 v1(112.9,136.75)
CP_UL: length 23.3
  TOP w0.2: IC7.32 112,135.25 112.15,135.4 v1(112.3,135.95) ; IC8.3 130.72,136.38 v1(129.85,137.25) R67.2
  BOTTOM w0.2: v1(129.85,137.25) 128.15,135.55 112.7,135.55 v1(112.3,135.95)
CP_VGS_U1: length 64.2
  TOP w0.2: TP17.1 70.25,129.4 71.45,128.2 71.45,119.9 71.9,119.45 71.9,118.15 76.25,113.8 94.5,113.8 96.5,115.8 96.5,122.75 99.25,125.5 IC7.65
  BOTTOM w0.2: Q4.1 R313.1 69.45,134.65 70.25,135.45 TP17.1
CP_VGS_U2: length 55.4
  TOP w0.2: TP18.1 70.25,120.15 71.5,118.9 71.5,117.9 76,113.4 94.7,113.4 96.9,115.6 96.9,122.55 99.35,125 IC7.66
  BOTTOM w0.2: TP18.1 70.25,126.2 69.45,125.4 R314.1 Q6.1
CP_VGS_U3: length 46.7
  TOP w0.2: TP19.1 75.75,113 94.9,113 97.3,115.4 97.3,122.35 99.45,124.5 IC7.67
  BOTTOM w0.2: TP19.1 70.25,116.95 69.45,116.15 R315.1 Q8.1
CP_VGS_U4: length 45.8
  TOP w0.2: IC7.68 100.35,124 100.25,124.1 99.65,124.1 97.7,122.15 97.7,115.2 95.1,112.6 76.3,112.6 72.95,109.25 TP20.1
  BOTTOM w0.2: TP20.1 70.25,107.7 69.45,106.9 R316.1 Q10.1
CP_VGS_U5: length 55.7
  TOP w0.2: TP21.1 67,102.65 76.55,112.2 95.3,112.2 98.1,115 98.1,121.35 99.65,122.9 100.25,122.9 100.35,123 IC7.70
  BOTTOM w0.2: R317.1 Q12.1 68.35,95.65 68.55,95.85 68.55,99.7 TP21.1
CP_VGS_U6: length 64.4
  TOP w0.2: IC7.71 99.85,122.5 98.5,121.15 98.5,114.8 95.5,111.8 76.75,111.8 68.15,103.2 68.15,93.15 TP22.1
  BOTTOM w0.2: TP22.1 68.55,90.45 68.55,86.6 68.35,86.4 Q14.1 R318.1
CP_VGS_U7: length 73.1
  TOP w0.2: TP23.1 68.55,84.3 68.55,103 76.95,111.4 95.7,111.4 98.9,114.6 98.9,120.95 99.95,122 IC7.72
  BOTTOM w0.2: TP23.1 68.55,81.2 68.55,77.35 68.35,77.15 Q16.1 R319.1
CP_VGS_U8: length 81.8
  TOP w0.2: TP24.1 68.95,75.45 68.95,102.8 77.15,111 95.9,111 99.3,114.4 99.3,120.75 100.05,121.5 IC7.73
  BOTTOM w0.2: R320.1 Q18.1 68.35,67.9 68.55,68.1 68.55,71.95 TP24.1
CP_VGS_V1: length 29.4
  TOP w0.2: TP33.1 88.1,110.6 97.05,110.6 97.7,109.95 101.85,109.95 103,111.1 IC7.76
  BOTTOM w0.2: Q20.1 R321.1 89.35,108.7 88.55,109.5 TP33.1
CP_VGS_V2: length 20.2
  TOP w0.2: TP34.1 102,109.5 103.5,111 IC7.77
  BOTTOM w0.2: TP34.1 97.8,109.5 98.6,108.7 R322.1 Q22.1
CP_VGS_V3: length 14.5
  TOP w0.2: IC7.78 104,111 TP35.1
  BOTTOM w0.2: Q24.1 R323.1 107.85,108.7 107.05,109.5 TP35.1
CP_VGS_V4: length 19.9
  TOP w0.2: IC7.79 104.5,116.6 110.15,110.95 113.3,110.95 TP36.1
  BOTTOM w0.2: Q26.1 R324.1 117.1,108.7 116.3,109.5 TP36.1
CP_VGS_V5: length 29.8
  TOP w0.2: TP37.1 122.7,107.45 118.45,107.45 114.55,111.35 110.35,111.35 105,116.7 IC7.80
  BOTTOM w0.2: TP37.1 123.85,107.85 124.4,108.4 R325.1 Q28.1
CP_VGS_V6: length 38.5
  TOP w0.2: IC7.81 105.5,116.8 110.55,111.75 114.75,111.75 118.65,107.85 131.55,107.85 TP38.1
  BOTTOM w0.2: Q30.1 R326.1 133.65,108.4 133.1,107.85 TP38.1
CP_VGS_V7: length 47.2
  TOP w0.2: IC7.82 106,116.9 110.75,112.15 114.95,112.15 118.85,108.25 140.4,108.25 TP39.1
  BOTTOM w0.2: TP39.1 142.35,107.85 142.9,108.4 R327.1 Q32.1
CP_VGS_V8: length 55.5
  TOP w0.2: TP40.1 149.25,108.65 119.05,108.65 115.15,112.55 110.95,112.55 107.4,116.1 107.4,117.6 107.5,117.7 IC7.85
  BOTTOM w0.2: Q34.1 R328.1 152.15,108.4 151.6,107.85 TP40.1
CP_VGS_W1: length 109.6
  TOP w0.2: TP49.1 175.8,73.2 175.8,101.25 167.2,109.85 118.45,109.85 115.35,112.95 112.3,112.95 109.6,115.65 109.6,117.65 109.5,117.75 IC7.89
  BOTTOM w0.2: Q36.1 R329.1 178.4,69.8 178.24,70.16 TP49.1
CP_VGS_W2: length 100.1
  TOP w0.2: IC7.90 110,115.85 112.5,113.35 115.55,113.35 118.65,110.25 167.4,110.25 176.2,101.45 176.2,82.05 TP50.1
  BOTTOM w0.2: TP50.1 178.24,79.41 178.4,79.05 R330.1 Q38.1
CP_VGS_W3: length 90.7
  TOP w0.2: TP51.1 177.75,92.05 176.65,93.15 176.65,101.6 167.6,110.65 118.85,110.65 115.75,113.75 112.7,113.75 110.5,115.95 IC7.91
  BOTTOM w0.2: TP51.1 178.24,88.66 178.4,88.3 R331.1 Q40.1
CP_VGS_W4: length 81.2
  TOP w0.2: IC7.92 111,116.1 112.95,114.15 115.95,114.15 119.05,111.05 167.85,111.05 177.75,101.15 TP52.1
  BOTTOM w0.2: Q42.1 R332.1 178.4,97.55 178.24,97.91 TP52.1
CP_VGS_W5: length 73.4
  TOP w0.2: IC7.93 111.5,116.2 113.15,114.55 116.15,114.55 119.25,111.45 169.05,111.45 TP53.1
  BOTTOM w0.2: TP53.1 173.75,108.5 174.35,109.1 R333.1 Q44.1
CP_VGS_W6: length 72.5
  TOP w0.2: IC7.94 112,116.3 113.35,114.95 116.35,114.95 119.45,111.85 169.6,111.85 TP54.1
  BOTTOM w0.2: Q46.1 R334.1 174.35,118.35 173.75,117.75 TP54.1
CP_VGS_W7: length 80.5
  TOP w0.2: IC7.95 112.5,116.4 113.55,115.35 116.55,115.35 119.65,112.25 169.4,112.25 172.4,115.25 172.4,123.9 TP55.1
  BOTTOM w0.2: TP55.1 173.75,127 174.35,127.6 R335.1 Q48.1
CP_VGS_W8: length 88.5
  TOP w0.2: IC7.96 113,116.5 113.75,115.75 116.75,115.75 119.85,112.65 169.2,112.65 172,115.45 172,132.75 TP56.1
  BOTTOM w0.2: TP56.1 173.75,136.25 174.35,136.85 R336.1 Q50.1
CP_VH: length 25.4
  TOP w0.2: IC7.33 111.5,135.35 111.7,135.55 v1(111.7,136.75) ; IC8.4 130.38,135.72 v1(129.85,136.25) R68.2
  BOTTOM w0.2: v1(111.7,136.75) 111.7,135.7 112.25,135.15 128.75,135.15 v1(129.85,136.25)
CP_VL: length 24.3
  TOP w0.2: IC8.5 130.26,135.07 v1(129.85,135.25) R69.2 ; v1(111.1,135.95) 111,135.51 IC7.34
  BOTTOM w0.2: v1(111.1,135.95) 111.1,135.3 111.65,134.75 129.35,134.75 v1(129.85,135.25)
CP_WH: length 26.4
  TOP w0.2: IC7.35 v1(110.5,136.75) ; R70.2 v1(129.85,134.25) 130.26,134.43 IC8.6
  BOTTOM w0.2: v1(129.85,134.25) 129.41,134.35 111.45,134.35 110.5,135.3 v1(110.5,136.75)
CP_WL: length 26.1
  TOP w0.2: IC8.7 130.38,133.78 v1(129.85,133.25) R71.2 ; v1(109.9,135.95) 110,135.51 IC7.36
  BOTTOM w0.2: v1(109.9,135.95) 109.9,135.3 111.3,133.9 128.7,133.9 129.35,133.25 v1(129.85,133.25)
CPLD_CLK: length 3.7
  TOP w0.2: IC7.22 R79.2
DBG_LED1: length 4.2
  TOP w0.2: DS1.K 101.33,135.85 103,135.85 103.5,135.35 IC7.49
DBG_LED2: length 5.2
  TOP w0.2: DS2.K 100.22,135.45 102.8,135.45 103,135.25 IC7.50
DBG_LED3: length 9
  TOP w0.2: IC7.52 100.35,132 100.25,131.9 97.35,131.9 96.85,132.4 96.85,135.53 DS3.K
DBG_LED4: length 9.3
  TOP w0.2: IC7.53 97.15,131.5 96.45,132.2 96.45,136.22 DS4.K
DBG_SW1: length 5.3
  TOP w0.2: IC7.54 100.3,131 100.2,131.1 96.5,131.1 R210.2
DBG_SW2: length 5.3
  TOP w0.2: IC7.55 100.15,130.5 99.95,130.7 96.75,130.7 96.5,130.45 R211.2
DBG_SW3: length 5.6
  TOP w0.2: IC7.56 100.05,130 99.75,130.3 96.95,130.3 R212.2
DBG_SW4: length 7.9
  TOP w0.2: R213.2 96.1,127.75 96.9,126.95 99.6,126.95 99.95,127.3 99.95,128.8 100.15,129 IC7.58
GD_U1: length 5.7
  TOP w0.5: R245.2 R214.1 54,135 53.5,134.5 Q3.4
  TOP w0.9: R176.2 R245.2
GD_U2: length 5.7
  TOP w0.5: Q5.4 53.5,125.25 54,125.75 R215.1 R246.2
  TOP w0.9: R177.2 R246.2
GD_U3: length 5.7
  TOP w0.5: R247.2 R216.1 54,116.5 53.5,116 Q7.4
  TOP w0.9: R178.2 R247.2
GD_U4: length 5.7
  TOP w0.5: Q9.4 53.5,106.75 54,107.25 R217.1 R249.2
  TOP w0.9: R179.2 R249.2
GD_U5: length 5.7
  TOP w0.5: Q11.4 53.5,93.9 54,94.4 R218.1 R251.2
  TOP w0.9: R180.2 R251.2
GD_U6: length 5.7
  TOP w0.5: R253.2 R219.1 54,85.15 53.5,84.65 Q13.4
  TOP w0.9: R181.2 R253.2
GD_U7: length 5.7
  TOP w0.5: R255.2 R220.1 54,75.9 53.5,75.4 Q15.4
  TOP w0.9: R182.2 R255.2
GD_U8: length 5.7
  TOP w0.5: R257.2 R221.1 54,66.65 53.5,66.15 Q17.4
  TOP w0.9: R183.2 R257.2
GD_V1: length 5.7
  TOP w0.5: R258.2 R222.1 89,93.25 89.5,92.75 Q19.4
  TOP w0.9: R168.2 R258.2
GD_V2: length 5.7
  TOP w0.5: Q21.4 98.75,92.75 98.25,93.25 R223.1 R260.2
  TOP w0.9: R169.2 R260.2
GD_V3: length 5.7
  TOP w0.5: R262.2 R224.1 107.5,93.25 108,92.75 Q23.4
  TOP w0.9: R170.2 R262.2
GD_V4: length 5.7
  TOP w0.5: R266.2 R225.1 116.75,93.25 117.25,92.75 Q25.4
  TOP w0.9: R171.2 R266.2
GD_V5: length 5.7
  TOP w0.5: Q27.4 130.1,92.75 129.6,93.25 R226.1 R264.2
  TOP w0.9: R172.2 R264.2
GD_V6: length 5.7
  TOP w0.5: Q29.4 139.35,92.75 138.85,93.25 R227.1 R268.2
  TOP w0.9: R173.2 R268.2
GD_V7: length 5.7
  TOP w0.5: Q31.4 148.6,92.75 148.1,93.25 R228.1 R270.2
  TOP w0.9: R174.2 R270.2
GD_V8: length 5.7
  TOP w0.5: Q33.4 157.85,92.75 157.35,93.25 R229.1 R272.2
  TOP w0.9: R175.2 R272.2
GD_W1: length 5.7
  TOP w0.5: R274.2 R230.1 190,68.15 190.5,68.65 Q35.4
  TOP w0.9: R184.2 R274.2
GD_W2: length 5.7
  TOP w0.5: R276.2 R231.1 190,77.4 190.5,77.9 Q37.4
  TOP w0.9: R185.2 R276.2
GD_W3: length 5.7
  TOP w0.5: Q39.4 190.5,87.15 190,86.65 R232.1 R278.2
  TOP w0.9: R186.2 R278.2
GD_W4: length 5.7
  TOP w0.5: Q41.4 190.5,96.4 190,95.9 R233.1 R280.2
  TOP w0.9: R187.2 R280.2
GD_W5: length 5.7
  TOP w0.5: Q43.4 190.5,109.25 190,108.75 R234.1 R282.2
  TOP w0.9: R188.2 R282.2
GD_W6: length 5.7
  TOP w0.5: R284.2 R235.1 190,118 190.5,118.5 Q45.4
  TOP w0.9: R189.2 R284.2
GD_W7: length 5.7
  TOP w0.5: R286.2 R236.1 190,127.25 190.5,127.75 Q47.4
  TOP w0.9: R190.2 R286.2
GD_W8: length 5.7
  TOP w0.5: R288.2 R237.1 190,136.5 190.5,137 Q49.4
  TOP w0.9: R191.2 R288.2
HVU_1_4: length 10.3
  BOTTOM w1.2: R196.1 8.65,87.4 C56.1 ; C54.2 11.85,104.4 R195.2
  vias: v2(31,118.05) v2(31,116.85) v2(31,115.65) v2(31,114.45) v2(31,113.25) v2(31,112.05) v2(31,110.85) v2(31,109.65) v2(31.1,73.85) v2(31.1,72.65) v2(31.1,71.45) v2(31.1,70.25) v2(31.1,69.05) v2(31.1,67.85) v2(31.1,66.65) v2(31.1,65.45) v2(32.2,118.05) v2(32.2,116.85) v2(32.2,115.65) v2(32.2,114.45) v2(32.2,113.25) v2(32.2,112.05) v2(32.2,110.85) v2(32.2,109.65) v2(32.3,73.85) v2(32.3,72.65) v2(32.3,71.45) v2(32.3,70.25) v2(32.3,69.05) v2(32.3,67.85) v2(32.3,66.65) v2(32.3,65.45) v2(33.4,118.05) v2(33.4,116.85) v2(33.4,115.65) v2(33.4,114.45) v2(33.4,113.25) v2(33.4,112.05) v2(33.4,110.85) v2(33.4,109.65) v2(33.5,73.85) v2(33.5,72.65) v2(33.5,71.45) v2(33.5,70.25) v2(33.5,69.05) v2(33.5,67.85) v2(33.5,66.65) v2(33.5,65.45) v2(34.6,118.05) v2(34.6,116.85) v2(34.6,115.65) v2(34.6,114.45) v2(34.6,113.25) v2(34.6,112.05) v2(34.6,110.85) v2(34.6,109.65) v2(34.7,73.85) v2(34.7,72.65) v2(34.7,71.45) v2(34.7,70.25) v2(34.7,69.05) v2(34.7,67.85) v2(34.7,66.65) v2(34.7,65.45) v2(35.8,118.05) v2(35.8,116.85) v2(35.8,115.65) v2(35.8,114.45) v2(35.8,113.25) v2(35.8,112.05) v2(35.8,110.85) v2(35.8,109.65) v2(35.9,73.85) v2(35.9,72.65) v2(35.9,71.45) v2(35.9,70.25) v2(35.9,69.05) v2(35.9,67.85) v2(35.9,66.65) v2(35.9,65.45)
HVU_2_4: length 10.3
  BOTTOM w1.2: R195.1 8.65,104.4 C54.1 ; C49.2 11.85,121.4 R194.2
  vias: v2(31,128.8) v2(31,127.6) v2(31,126.4) v2(31,125.2) v2(31,124) v2(31,122.8) v2(31,121.6) v2(31,120.4) v2(31.1,84.6) v2(31.1,83.4) v2(31.1,82.2) v2(31.1,81) v2(31.1,79.8) v2(31.1,78.6) v2(31.1,77.4) v2(31.1,76.2) v2(32.2,128.8) v2(32.2,127.6) v2(32.2,126.4) v2(32.2,125.2) v2(32.2,124) v2(32.2,122.8) v2(32.2,121.6) v2(32.2,120.4) v2(32.3,84.6) v2(32.3,83.4) v2(32.3,82.2) v2(32.3,81) v2(32.3,79.8) v2(32.3,78.6) v2(32.3,77.4) v2(32.3,76.2) v2(33.4,128.8) v2(33.4,127.6) v2(33.4,126.4) v2(33.4,125.2) v2(33.4,124) v2(33.4,122.8) v2(33.4,121.6) v2(33.4,120.4) v2(33.5,84.6) v2(33.5,83.4) v2(33.5,82.2) v2(33.5,81) v2(33.5,79.8) v2(33.5,78.6) v2(33.5,77.4) v2(33.5,76.2) v2(34.6,128.8) v2(34.6,127.6) v2(34.6,126.4) v2(34.6,125.2) v2(34.6,124) v2(34.6,122.8) v2(34.6,121.6) v2(34.6,120.4) v2(34.7,84.6) v2(34.7,83.4) v2(34.7,82.2) v2(34.7,81) v2(34.7,79.8) v2(34.7,78.6) v2(34.7,77.4) v2(34.7,76.2) v2(35.8,128.8) v2(35.8,127.6) v2(35.8,126.4) v2(35.8,125.2) v2(35.8,124) v2(35.8,122.8) v2(35.8,121.6) v2(35.8,120.4) v2(35.9,84.6) v2(35.9,83.4) v2(35.9,82.2) v2(35.9,81) v2(35.9,79.8) v2(35.9,78.6) v2(35.9,77.4) v2(35.9,76.2)
HVU_3_4: length 10.3
  BOTTOM w1.2: 18.6,131.25 R193.2 18.6,133.35 C48.2 ; R194.1 8.65,121.4 C49.1
  vias: v2(28.6,137.25) v2(28.6,136.05) v2(28.6,134.85) v2(28.6,133.65) v2(28.6,132.45) v2(28.6,131.25) v2(29.8,137.25) v2(29.8,136.05) v2(29.8,134.85) v2(29.8,133.65) v2(29.8,132.45) v2(29.8,131.25) v2(31,137.25) v2(31,136.05) v2(31,134.85) v2(31,133.65) v2(31,132.45) v2(31,131.25) v2(31.1,95.35) v2(31.1,94.15) v2(31.1,92.95) v2(31.1,91.75) v2(31.1,90.55) v2(31.1,89.35) v2(31.1,88.15) v2(31.1,86.95) v2(32.2,137.25) v2(32.2,136.05) v2(32.2,134.85) v2(32.2,133.65) v2(32.2,132.45) v2(32.2,131.25) v2(32.3,95.35) v2(32.3,94.15) v2(32.3,92.95) v2(32.3,91.75) v2(32.3,90.55) v2(32.3,89.35) v2(32.3,88.15) v2(32.3,86.95) v2(33.4,137.25) v2(33.4,136.05) v2(33.4,134.85) v2(33.4,133.65) v2(33.4,132.45) v2(33.4,131.25) v2(33.5,95.35) v2(33.5,94.15) v2(33.5,92.95) v2(33.5,91.75) v2(33.5,90.55) v2(33.5,89.35) v2(33.5,88.15) v2(33.5,86.95) v2(34.6,137.25) v2(34.6,136.05) v2(34.6,134.85) v2(34.6,133.65) v2(34.6,132.45) v2(34.6,131.25) v2(34.7,95.35) v2(34.7,94.15) v2(34.7,92.95) v2(34.7,91.75) v2(34.7,90.55) v2(34.7,89.35) v2(34.7,88.15) v2(34.7,86.95) v2(35.8,137.25) v2(35.8,136.05) v2(35.8,134.85) v2(35.8,133.65) v2(35.8,132.45) v2(35.8,131.25) v2(35.9,95.35) v2(35.9,94.15) v2(35.9,92.95) v2(35.9,91.75) v2(35.9,90.55) v2(35.9,89.35) v2(35.9,88.15) v2(35.9,86.95)
HVV_1_4: length 9.5
  BOTTOM w1.3: C71.1 152.9,56.35 R202.1 ; C69.2 139.35,55.9 R201.2
  vias: v2(105.95,75.05) v2(105.95,73.85) v2(105.95,72.65) v2(105.95,71.45) v2(105.95,70.25) v2(107.15,75.05) v2(107.15,73.85) v2(107.15,72.65) v2(107.15,71.45) v2(107.15,70.25) v2(108.35,75.05) v2(108.35,73.85) v2(108.35,72.65) v2(108.35,71.45) v2(108.35,70.25) v2(109.55,75.05) v2(109.55,73.85) v2(109.55,72.65) v2(109.55,71.45) v2(109.55,70.25) v2(110.75,75.05) v2(110.75,73.85) v2(110.75,72.65) v2(110.75,71.45) v2(110.75,70.25) v2(111.95,75.05) v2(111.95,73.85) v2(111.95,72.65) v2(111.95,71.45) v2(111.95,70.25) v2(113.15,75.05) v2(113.15,73.85) v2(113.15,72.65) v2(113.15,71.45) v2(113.15,70.25) v2(114.35,75.05) v2(114.35,73.85) v2(114.35,72.65) v2(114.35,71.45) v2(114.35,70.25) v2(150.15,75.15) v2(150.15,73.95) v2(150.15,72.75) v2(150.15,71.55) v2(150.15,70.35) v2(150.15,69.15) v2(151.35,75.15) v2(151.35,73.95) v2(151.35,72.75) v2(151.35,71.55) v2(151.35,70.35) v2(151.35,69.15) v2(151.35,67.95) v2(152.55,75.15) v2(152.55,73.95) v2(152.55,72.75) v2(152.55,71.55) v2(152.55,70.35) v2(152.55,69.15) v2(152.55,67.95) v2(153.75,75.15) v2(153.75,73.95) v2(153.75,72.75) v2(153.75,71.55) v2(153.75,70.35) v2(153.75,69.15) v2(153.75,67.95) v2(154.95,75.15) v2(154.95,73.95) v2(154.95,72.75) v2(154.95,71.55) v2(154.95,70.35) v2(154.95,69.15) v2(154.95,67.95) v2(156.15,75.15) v2(156.15,73.95) v2(156.15,72.75) v2(156.15,71.55) v2(156.15,70.35) v2(156.15,69.15)
HVV_2_4: length 10.3
  BOTTOM w1.3: C65.2 107.35,55.9 R200.2 ; R201.1 136.15,55.9 C69.1
  vias: v2(95.2,75.05) v2(95.2,73.85) v2(95.2,72.65) v2(95.2,71.45) v2(95.2,70.25) v2(96.4,75.05) v2(96.4,73.85) v2(96.4,72.65) v2(96.4,71.45) v2(96.4,70.25) v2(97.6,75.05) v2(97.6,73.85) v2(97.6,72.65) v2(97.6,71.45) v2(97.6,70.25) v2(98.8,75.05) v2(98.8,73.85) v2(98.8,72.65) v2(98.8,71.45) v2(98.8,70.25) v2(100,75.05) v2(100,73.85) v2(100,72.65) v2(100,71.45) v2(100,70.25) v2(101.2,75.05) v2(101.2,73.85) v2(101.2,72.65) v2(101.2,71.45) v2(101.2,70.25) v2(102.4,75.05) v2(102.4,73.85) v2(102.4,72.65) v2(102.4,71.45) v2(102.4,70.25) v2(103.6,75.05) v2(103.6,73.85) v2(103.6,72.65) v2(103.6,71.45) v2(103.6,70.25) v2(139.4,75.15) v2(139.4,73.95) v2(139.4,72.75) v2(139.4,71.55) v2(139.4,70.35) v2(140.6,75.15) v2(140.6,73.95) v2(140.6,72.75) v2(140.6,71.55) v2(140.6,70.35) v2(141.8,75.15) v2(141.8,73.95) v2(141.8,72.75) v2(141.8,71.55) v2(141.8,70.35) v2(143,75.15) v2(143,73.95) v2(143,72.75) v2(143,71.55) v2(143,70.35) v2(144.2,75.15) v2(144.2,73.95) v2(144.2,72.75) v2(144.2,71.55) v2(144.2,70.35) v2(145.4,75.15) v2(145.4,73.95) v2(145.4,72.75) v2(145.4,71.55) v2(145.4,70.35) v2(146.6,75.15) v2(146.6,73.95) v2(146.6,72.75) v2(146.6,71.55) v2(146.6,70.35) v2(147.8,75.15) v2(147.8,73.95) v2(147.8,72.75) v2(147.8,71.55) v2(147.8,70.35)
HVV_3_4: length 10.3
  BOTTOM w1.3: R200.1 104.15,55.9 C65.1 ; C63.2 90.35,55.9 R199.2
  vias: v2(85.55,75.05) v2(85.55,73.85) v2(85.55,72.65) v2(85.55,71.45) v2(85.55,70.25) v2(85.55,69.05) v2(86.75,75.05) v2(86.75,73.85) v2(86.75,72.65) v2(86.75,71.45) v2(86.75,70.25) v2(86.75,69.05) v2(87.95,75.05) v2(87.95,73.85) v2(87.95,72.65) v2(87.95,71.45) v2(87.95,70.25) v2(87.95,69.05) v2(89.15,75.05) v2(89.15,73.85) v2(89.15,72.65) v2(89.15,71.45) v2(89.15,70.25) v2(89.15,69.05) v2(90.35,75.05) v2(90.35,73.85) v2(90.35,72.65) v2(90.35,71.45) v2(90.35,70.25) v2(90.35,69.05) v2(91.55,75.05) v2(91.55,73.85) v2(91.55,72.65) v2(91.55,71.45) v2(91.55,70.25) v2(91.55,69.05) v2(92.75,75.05) v2(92.75,73.85) v2(92.75,72.65) v2(92.75,71.45) v2(92.75,70.25) v2(92.75,69.05) v2(128.65,75.15) v2(128.65,73.95) v2(128.65,72.75) v2(128.65,71.55) v2(128.65,70.35) v2(129.85,75.15) v2(129.85,73.95) v2(129.85,72.75) v2(129.85,71.55) v2(129.85,70.35) v2(131.05,75.15) v2(131.05,73.95) v2(131.05,72.75) v2(131.05,71.55) v2(131.05,70.35) v2(132.25,75.15) v2(132.25,73.95) v2(132.25,72.75) v2(132.25,71.55) v2(132.25,70.35) v2(133.45,75.15) v2(133.45,73.95) v2(133.45,72.75) v2(133.45,71.55) v2(133.45,70.35) v2(134.65,75.15) v2(134.65,73.95) v2(134.65,72.75) v2(134.65,71.55) v2(134.65,70.35) v2(135.85,75.15) v2(135.85,73.95) v2(135.85,72.75) v2(135.85,71.55) v2(135.85,70.35) v2(137.05,75.15) v2(137.05,73.95) v2(137.05,72.75) v2(137.05,71.55) v2(137.05,70.35)
